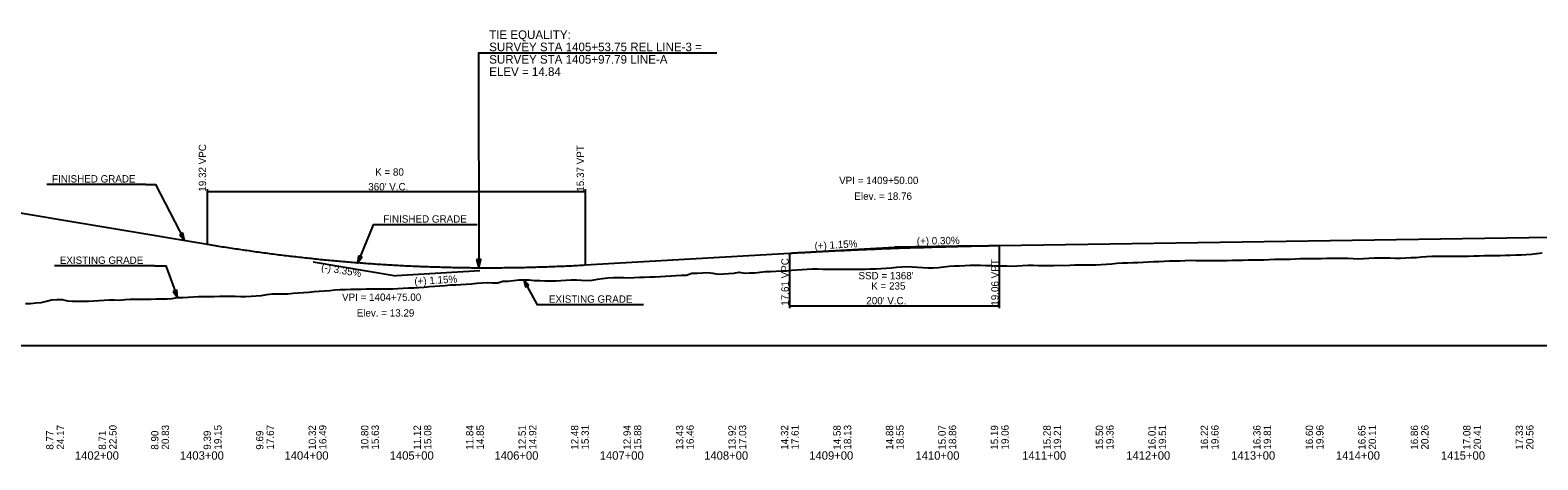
# Model space of a CAD drawing. Extents: x 2360994 to 2383826, y 330623 to 403123.
# Drawn here: x 2371652 to 2373088, y 351764 to 352173 of the extents above; entities that cross this region are included whole.
import ezdxf

# ---------------------------------------------------------------- set-up
doc = ezdxf.new("R2010")
doc.units = 0
for name, color, linetype in [('RD_DDB_GradeTX', 7, 'Continuous'), ('RD_DDB_Profile_EX', 7, 'Continuous'), ('RD_DDB_Profile_Lbl', 7, 'Continuous'), ('RD_DDB_Profile_PR', 7, 'Continuous'), ('RD_DDB_StaTX', 7, 'Continuous'), ('RD_DDB_StripGrade', 7, 'Continuous'), ('RD_DDB_VCLbl', 7, 'Continuous'), ('RD_GPK_Profile_Cell', 7, 'Continuous'), ('RD_TX_Profile', 7, 'Continuous')]:
    doc.layers.add(name, color=color, linetype=linetype)

msp = doc.modelspace()

# ---------------------------------------------------------------- linework, layer by layer
at = {"layer": 'RD_DDB_GradeTX'}
for p, q in [((2372395.7, 351962.1), (2372475.6, 351966.7)), ((2372555.6, 351967.9), (2372475.6, 351966.7)), ((2371921.7, 351952.6), (2372000.6, 351939.4)), ((2372080.4, 351944), (2372000.6, 351939.4))]:
    msp.add_line(p, q, dxfattribs=at)
at = {"layer": 'RD_DDB_Profile_EX'}
for points in [[(2372417.4, 351945.8), (2372422.4, 351945.7), (2372427.4, 351945.8), (2372432.4, 351945.8), (2372437.4, 351945.8), (2372442.4, 351945.8), (2372447.4, 351945.7), (2372452.4, 351945.9), (2372457.4, 351946.1), (2372462.4, 351946.3), (2372467.4, 351946.5), (2372472.4, 351947), (2372477.4, 351947.5), (2372482.4, 351948), (2372487.4, 351948.2), (2372492.4, 351947.9), (2372497.4, 351947.7), (2372502.4, 351947.4), (2372507.4, 351947.1), (2372512.4, 351946.9), (2372517.4, 351947.2), (2372522.4, 351947.8), (2372527.4, 351948.4), (2372532.4, 351949), (2372537.4, 351948.9), (2372542.4, 351949.2), (2372547.4, 351949.5), (2372552.4, 351949.6), (2372557.4, 351949.5), (2372562.4, 351949.3), (2372567.4, 351949.1), (2372572.4, 351949), (2372577.4, 351948.8), (2372582.4, 351948.8), (2372587.4, 351948.6), (2372592.4, 351948.9), (2372597.4, 351949.1), (2372602.4, 351949.6), (2372607.4, 351949.4), (2372612.4, 351949.3), (2372617.4, 351949.1), (2372622.4, 351949.2), (2372627.4, 351949.3), (2372632.4, 351949.4), (2372637.4, 351949.3), (2372642.4, 351949.5), (2372647.4, 351949.8), (2372652.4, 351949.8), (2372657.4, 351949.8), (2372662.4, 351949.8), (2372667.4, 351949.9), (2372672.4, 351950.2), (2372677.4, 351950.5), (2372682.4, 351950.7), (2372687.4, 351951.3), (2372692.4, 351951.8), (2372697.4, 351951.7), (2372702.4, 351951.9), (2372707.4, 351952.1), (2372712.4, 351952.3), (2372717.4, 351952.6), (2372722.4, 351952.9), (2372727.4, 351952.9), (2372732.4, 351953.4), (2372737.4, 351953.6), (2372742.4, 351953.6), (2372747.4, 351953.7), (2372752.4, 351953.9), (2372757.4, 351954.1), (2372762.4, 351953.9), (2372767.4, 351954), (2372772.4, 351954), (2372777.4, 351954), (2372782.4, 351953.9), (2372787.4, 351953.9), (2372792.4, 351954), (2372797.4, 351954.1), (2372802.4, 351954.2), (2372807.4, 351954.4), (2372812.4, 351954.5), (2372817.4, 351954.7), (2372822.4, 351954.6), (2372827.4, 351954.7), (2372832.4, 351955), (2372837.4, 351955.1), (2372842.4, 351955.1), (2372847.4, 351955.1), (2372852.4, 351955.3), (2372857.4, 351955.5), (2372862.4, 351955.7), (2372867.4, 351955.8), (2372872.4, 351955.8), (2372877.4, 351955.9), (2372882.4, 351955.9), (2372887.4, 351956.2), (2372892.4, 351956.3), (2372897.4, 351956.1), (2372902.4, 351956), (2372907.4, 351956.2), (2372912.4, 351955.9), (2372917.4, 351955.5)], [(2372917.4, 351955.5), (2372922.4, 351955.8), (2372927.4, 351956.3), (2372932.4, 351956.4), (2372937.4, 351956.4), (2372942.4, 351956.5), (2372947.4, 351956.5), (2372952.4, 351956.3), (2372957.4, 351956.3), (2372962.4, 351956.5), (2372967.4, 351956.7), (2372972.4, 351956.9), (2372977.4, 351957.3), (2372982.4, 351957.8), (2372987.4, 351958.1), (2372992.4, 351958.1), (2372997.4, 351958), (2373002.4, 351958), (2373007.4, 351958), (2373012.4, 351957.9), (2373017.4, 351958), (2373022.4, 351958.2), (2373027.4, 351958.3), (2373032.4, 351958.5), (2373037.4, 351958.6), (2373042.4, 351958.7), (2373047.4, 351958.7), (2373052.4, 351958.8), (2373057.4, 351958.9), (2373062.4, 351959.1), (2373067.4, 351959.2), (2373072.4, 351959.4), (2373077.4, 351959.6), (2373082.4, 351959.9), (2373087.4, 351960.7), (2373092.4, 351961.1)], [(2371917.4, 351923.9), (2371922.4, 351924.3), (2371927.4, 351924.6), (2371932.4, 351925.1), (2371937.4, 351925.5), (2371942.4, 351926), (2371947.4, 351926.4), (2371952.4, 351926.4), (2371957.4, 351926.5), (2371962.4, 351926.5), (2371967.4, 351926.6), (2371972.4, 351926.8), (2371977.4, 351926.9), (2371982.4, 351927), (2371987.4, 351927), (2371992.4, 351927.1), (2371997.4, 351926.8), (2372002.4, 351927.2), (2372007.4, 351927.5), (2372012.4, 351927.9), (2372017.4, 351928), (2372022.4, 351928.2), (2372027.4, 351928.6), (2372032.4, 351929.1), (2372037.4, 351929.4), (2372042.4, 351929.7), (2372047.4, 351930.1), (2372052.4, 351930.6), (2372057.4, 351930.9), (2372062.4, 351931.2), (2372067.4, 351931.5), (2372072.4, 351931.7), (2372077.4, 351932.3), (2372082.4, 351932.8), (2372087.4, 351933.1), (2372092.4, 351932.8), (2372097.4, 351932.8), (2372102.4, 351934.3), (2372107.4, 351934.3), (2372112.4, 351934.8), (2372117.4, 351935.4), (2372122.4, 351935.5), (2372127.4, 351935.4), (2372132.4, 351935), (2372137.4, 351934.8), (2372142.4, 351934.7), (2372147.4, 351934.6), (2372152.4, 351934.7), (2372157.4, 351935), (2372162.4, 351935.3), (2372167.4, 351935.4), (2372172.4, 351935.5), (2372177.4, 351935.2), (2372182.4, 351934.8), (2372187.4, 351935.3), (2372192.4, 351936), (2372197.4, 351936.8), (2372202.4, 351937.3), (2372207.4, 351937.6), (2372212.4, 351937.8), (2372217.4, 351937.6), (2372222.4, 351937.5), (2372227.4, 351937.7), (2372232.4, 351937.9), (2372237.4, 351938.1), (2372242.4, 351938.3), (2372247.4, 351938.5), (2372252.4, 351938.8), (2372257.4, 351939.1), (2372262.4, 351939.4), (2372267.4, 351939.7), (2372272.4, 351939.9), (2372277.4, 351940.1), (2372282.4, 351941.8), (2372287.4, 351942), (2372292.4, 351942.3), (2372297.4, 351942.5), (2372302.4, 351942), (2372307.4, 351940.9), (2372312.4, 351941.2), (2372317.4, 351941.5), (2372322.4, 351941.8), (2372327.4, 351942.8), (2372332.4, 351941.9), (2372337.4, 351942.1), (2372342.4, 351942.2), (2372347.4, 351942.9), (2372352.4, 351943.4), (2372357.4, 351943.6), (2372362.4, 351943.8), (2372367.4, 351944), (2372372.4, 351944.2), (2372377.4, 351944.7), (2372382.4, 351945), (2372387.4, 351945.4), (2372392.4, 351945.8), (2372397.4, 351945.9), (2372402.4, 351945.9), (2372407.4, 351945.8), (2372412.4, 351945.8), (2372417.4, 351945.8)], [(2371647.4, 351912.9), (2371652.4, 351913.1), (2371657.4, 351913.5), (2371662.4, 351913.9), (2371667.4, 351915.1), (2371672.4, 351916.5), (2371677.4, 351916.9), (2371682.4, 351916.7), (2371687.4, 351915.6), (2371692.4, 351915.3), (2371697.4, 351915.2), (2371702.4, 351915.2), (2371707.4, 351915.2), (2371712.4, 351915.4), (2371717.4, 351915.7), (2371722.4, 351916.1), (2371727.4, 351916.6), (2371732.4, 351916.4), (2371737.4, 351916.3), (2371742.4, 351916.7), (2371747.4, 351917), (2371752.4, 351917.2), (2371757.4, 351917.1), (2371762.4, 351917.1), (2371767.4, 351917.2), (2371772.4, 351917.3), (2371777.4, 351917.4), (2371782.4, 351917.5), (2371787.4, 351917.6), (2371792.4, 351918.6), (2371797.4, 351918.8), (2371802.4, 351918.9), (2371807.4, 351919.3), (2371812.4, 351919.6), (2371817.4, 351919.8), (2371822.4, 351919.8), (2371827.4, 351919.8), (2371832.4, 351919.9), (2371837.4, 351919.9), (2371842.4, 351920), (2371847.4, 351919.9), (2371852.4, 351919.7), (2371857.4, 351919.7), (2371862.4, 351920), (2371867.4, 351920.3), (2371872.4, 351920.7), (2371877.4, 351921.7), (2371882.4, 351922.2), (2371887.4, 351922.1), (2371892.4, 351922.1), (2371897.4, 351922.3), (2371902.4, 351922.8), (2371907.4, 351923.2), (2371912.4, 351923.5), (2371917.4, 351923.9)]]:
    msp.add_lwpolyline(points, dxfattribs=at)
at = {"layer": 'RD_DDB_Profile_PR'}
for p, q in [((2371545.6, 352015.5), (2371830.6, 351967.8)), ((2372575.6, 351968.2), (2373100.6, 351976)), ((2372180.6, 351949.7), (2372375.6, 351960.9))]:
    msp.add_line(p, q, dxfattribs=at)
for points in [[(2371820.6, 351969.5), (2371827.8, 351968.3), (2371835, 351967.1), (2371842.2, 351966), (2371849.4, 351964.9), (2371856.6, 351963.9), (2371863.8, 351962.8), (2371871, 351961.8), (2371878.2, 351960.9), (2371885.4, 351959.9), (2371892.6, 351959), (2371899.8, 351958.2), (2371907, 351957.4), (2371914.2, 351956.6), (2371921.4, 351955.8), (2371928.6, 351955), (2371935.8, 351954.3), (2371943, 351953.7), (2371950.2, 351953), (2371957.4, 351952.4), (2371964.6, 351951.9), (2371971.8, 351951.3), (2371979, 351950.8), (2371986.2, 351950.3), (2371993.4, 351949.9), (2372000.6, 351949.5), (2372007.8, 351949.1), (2372015, 351948.7), (2372022.2, 351948.4), (2372029.4, 351948.2), (2372036.6, 351947.9), (2372043.8, 351947.7), (2372051, 351947.5), (2372058.2, 351947.3), (2372065.4, 351947.2), (2372072.6, 351947.1), (2372079.8, 351947.1), (2372087, 351947.1), (2372094.2, 351947.1), (2372101.4, 351947.1), (2372108.6, 351947.2), (2372115.8, 351947.3), (2372123, 351947.4), (2372130.2, 351947.6), (2372137.4, 351947.8), (2372144.6, 351948), (2372151.8, 351948.3), (2372159, 351948.6), (2372166.2, 351948.9), (2372173.4, 351949.3), (2372180.6, 351949.7)], [(2372375.6, 351960.9), (2372379.6, 351961.2), (2372383.6, 351961.4), (2372387.6, 351961.6), (2372391.6, 351961.8), (2372395.6, 351962), (2372399.6, 351962.2), (2372403.6, 351962.5), (2372407.6, 351962.7), (2372411.6, 351962.9), (2372415.6, 351963.1), (2372419.6, 351963.3), (2372423.6, 351963.4), (2372427.6, 351963.6), (2372431.6, 351963.8), (2372435.6, 351964), (2372439.6, 351964.2), (2372443.6, 351964.3), (2372447.6, 351964.5), (2372451.6, 351964.7), (2372455.6, 351964.8), (2372459.6, 351965), (2372463.6, 351965.2), (2372467.6, 351965.3), (2372471.6, 351965.5), (2372475.6, 351965.6), (2372479.6, 351965.8), (2372483.6, 351965.9), (2372487.6, 351966), (2372491.6, 351966.2), (2372495.6, 351966.3), (2372499.6, 351966.4), (2372503.6, 351966.5), (2372507.6, 351966.7), (2372511.6, 351966.8), (2372515.6, 351966.9), (2372519.6, 351967), (2372523.6, 351967.1), (2372527.6, 351967.2), (2372531.6, 351967.3), (2372535.6, 351967.4), (2372539.6, 351967.5), (2372543.6, 351967.6), (2372547.6, 351967.7), (2372551.6, 351967.8), (2372555.6, 351967.8), (2372559.6, 351967.9), (2372563.6, 351968), (2372567.6, 351968.1), (2372571.6, 351968.1), (2372575.6, 351968.2)]]:
    msp.add_spline(points, degree=3, dxfattribs=at)
at = {"layer": 'RD_DDB_VCLbl'}
for p, q in [((2371820.6, 352022), (2371820.6, 351969.5)), ((2371820.6, 352019.5), (2372180.6, 352019.5)), ((2372180.6, 352022), (2372180.6, 351949.7)), ((2372575.6, 351908.4), (2372575.6, 351968.2)), ((2372375.6, 351908.4), (2372375.6, 351960.9)), ((2372375.6, 351910.9), (2372575.6, 351910.9))]:
    msp.add_line(p, q, dxfattribs=at)
at = {"layer": 'RD_GPK_Profile_Cell'}
msp.add_line((2368825.6, 351872.9), (2374525.6, 351872.9), dxfattribs=at)
at = {"layer": 'RD_TX_Profile'}
for p, q in [((2372306.1, 352151.4), (2372084.3, 352151.4)), ((2371762.3, 352026.2), (2371667.8, 352026.2)), ((2372078, 351988), (2371983.4, 351988)), ((2371770.4, 351948.7), (2371675.2, 351948.7)), ((2372236.3, 351911.7), (2372141.2, 351911.7))]:
    msp.add_line(p, q, dxfattribs=at)
for points in [[(2372084.3, 352151.4), (2372079, 352151.4), (2372079.3, 351947.1)], [(2371762.3, 352026.2), (2371771.3, 352026.2), (2371798.9, 351973.1)], [(2371983.4, 351988), (2371978.9, 351988), (2371963.9, 351951.5)], [(2371770.4, 351948.7), (2371781.1, 351948.7), (2371792.4, 351918.6)], [(2372141.2, 351911.7), (2372135.4, 351911.7), (2372122.4, 351935.5)]]:
    msp.add_lwpolyline(points, dxfattribs=at)
for points in [[(2371794.1, 351978.2), (2371798.9, 351973.1), (2371797.4, 351979.9)], [(2371964.8, 351958.4), (2371963.9, 351951.5), (2371968.1, 351957.1)], [(2372077.2, 351955), (2372079.3, 351947.1), (2372081.4, 351955)], [(2372127.2, 351930.5), (2372122.4, 351935.5), (2372124, 351928.7)], [(2371788.3, 351924.3), (2371792.4, 351918.6), (2371791.7, 351925.6)]]:
    msp.add_lwpolyline(points, close=True, dxfattribs=at)

# ---------------------------------------------------------------- texts
at = {"layer": 'RD_DDB_GradeTX'}
for s, rotation, p in [('(+) 0.30%', 0.8587, (2372496.7, 351969)), ('(+) 1.15%', 3.2924, (2372399.5, 351964.3)), ('(-) 3.35%', 350.5, (2371928.9, 351944.4)), ('(+) 1.15%', 3.2924, (2372018.2, 351930.6))]:
    msp.add_text(s, height=7, rotation=rotation, dxfattribs=at).set_placement(p)
at = {"layer": 'RD_DDB_Profile_Lbl'}
for s, p in [('VPI = 1409+50.00', (2372422.7, 352026.7)), ('Elev. = 18.76', (2372437.2, 352011.7)), ('VPI = 1404+75.00', (2371949.1, 351915.5)), ('Elev. = 13.29', (2371963.1, 351900.5))]:
    msp.add_text(s, height=7, dxfattribs=at).set_placement(p)
at = {"layer": 'RD_DDB_StaTX'}
for s, p in [('1402+00', (2371694.6, 351764.2)), ('1403+00', (2371794.6, 351764.2)), ('1404+00', (2371894.3, 351764.2)), ('1405+00', (2371994.5, 351764.2)), ('1406+00', (2372094.3, 351764.2)), ('1407+00', (2372194.6, 351764.2)), ('1408+00', (2372294.1, 351764.2)), ('1409+00', (2372394.2, 351764.2)), ('1410+00', (2372495.4, 351764.2)), ('1411+00', (2372597, 351764.2)), ('1412+00', (2372696.2, 351764.2)), ('1413+00', (2372796.2, 351764.2)), ('1414+00', (2372896, 351764.2)), ('1415+00', (2372996.1, 351764.2))]:
    msp.add_text(s, height=8, dxfattribs=at).set_placement(p)
at = {"layer": 'RD_DDB_StripGrade'}
for s, p in [('19.32 VPC', (2371819.6, 352019.5)), ('15.37 VPT', (2372179.6, 352019.5)), ('17.61 VPC', (2372374.6, 351910.9)), ('19.06 VPT', (2372574.6, 351910.9)), ('8.77', (2371674.2, 351773.7)), ('24.17', (2371684.3, 351773.9)), ('8.71', (2371724.2, 351773.7)), ('22.50', (2371734.3, 351773.9)), ('8.90', (2371774.2, 351773.7)), ('20.83', (2371784.3, 351773.9)), ('9.39', (2371824.2, 351773.7)), ('19.15', (2371834.3, 351773.9)), ('9.69', (2371874.2, 351773.7)), ('17.67', (2371884.2, 351773.9)), ('10.32', (2371924.2, 351773.7)), ('16.49', (2371934.2, 351773.9)), ('10.80', (2371974.2, 351773.7)), ('15.63', (2371984.2, 351773.9)), ('11.12', (2372024.2, 351773.7)), ('15.08', (2372034.2, 351773.9)), ('11.84', (2372074.2, 351773.7)), ('14.85', (2372084.2, 351773.9)), ('12.51', (2372124.2, 351773.7)), ('14.92', (2372134.2, 351773.9)), ('12.48', (2372174.2, 351773.7)), ('15.31', (2372184.2, 351773.9)), ('12.94', (2372224.2, 351773.7)), ('15.88', (2372234.2, 351773.9)), ('13.43', (2372274.2, 351773.7)), ('16.46', (2372284.2, 351773.9)), ('13.92', (2372324.2, 351773.7)), ('17.03', (2372334.2, 351773.9)), ('14.32', (2372374.2, 351773.7)), ('17.61', (2372384.2, 351773.9)), ('14.58', (2372424.2, 351773.7)), ('18.13', (2372434.2, 351773.9)), ('14.88', (2372474.2, 351773.7)), ('18.55', (2372484.2, 351773.9)), ('15.07', (2372524.2, 351773.7)), ('18.86', (2372534.2, 351773.9)), ('15.19', (2372574.2, 351773.7)), ('19.06', (2372584.2, 351773.9)), ('15.28', (2372624.2, 351773.7)), ('19.21', (2372634.2, 351773.9)), ('15.50', (2372674.2, 351773.7)), ('19.36', (2372684.2, 351773.9)), ('16.01', (2372724.2, 351773.7)), ('19.51', (2372734.2, 351773.9)), ('16.22', (2372774.2, 351773.7)), ('19.66', (2372784.2, 351773.9)), ('16.36', (2372824.2, 351773.7)), ('19.81', (2372834.2, 351773.9)), ('16.60', (2372874.2, 351773.7)), ('19.96', (2372884.2, 351773.9)), ('16.65', (2372924.2, 351773.7)), ('20.11', (2372934.2, 351773.9)), ('16.86', (2372974.2, 351773.7)), ('20.26', (2372984.2, 351773.9)), ('17.08', (2373024.2, 351773.7)), ('20.41', (2373034.2, 351773.9)), ('17.33', (2373074.2, 351773.7)), ('20.56', (2373084.2, 351773.9))]:
    msp.add_text(s, height=7, rotation=90, dxfattribs=at).set_placement(p)
at = {"layer": 'RD_DDB_VCLbl'}
for s, p in [('K = 80', (2371980.7, 352034.7)), ("360' V.C.", (2371974.1, 352020.7)), ("SSD = 1368'", (2372441.1, 351936)), ('K = 235', (2372453.3, 351926.2)), ("200' V.C.", (2372448.6, 351912.2))]:
    msp.add_text(s, height=7, dxfattribs=at).set_placement(p)
at = {"layer": 'RD_TX_Profile'}
for s, height, p in [('TIE EQUALITY:', 8.235, (2372089.3, 352164.9)), ('SURVEY STA 1405+53.75 REL LINE-3 =', 8.235, (2372089.3, 352153.2)), ('SURVEY STA 1405+97.79 LINE-A', 8.235, (2372089.3, 352141.4)), ('ELEV = 14.84', 8.235, (2372089.3, 352129.6)), ('FINISHED GRADE', 7, (2371672.8, 352028.2)), ('FINISHED GRADE', 7, (2371988.4, 351990)), ('EXISTING GRADE', 7, (2371680.2, 351950.7)), ('EXISTING GRADE', 7, (2372146.2, 351913.7))]:
    msp.add_text(s, height=height, dxfattribs=at).set_placement(p)

doc.saveas('drawing.dxf')
